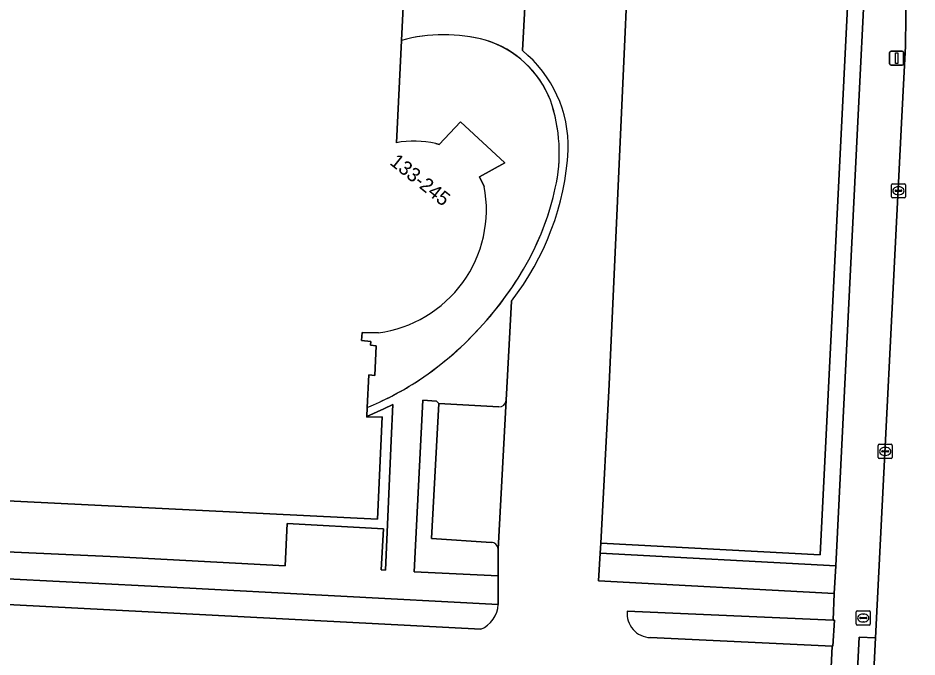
# Model space of a CAD drawing. Extents: x 161758 to 162722, y 384793 to 385405.
# Drawn here: x 162064.1 to 162127.8, y 385280.9 to 385326.1 of the extents above; entities that cross this region are included whole.
import ezdxf

# ---------------------------------------------------------------- set-up
doc = ezdxf.new("R2010")
doc.units = 0
for name, color, linetype in [('IMGEO_Brandkraan', 7, 'Continuous'), ('IMGEO_Erf', 7, 'Continuous'), ('IMGEO_Groenvoorziening', 7, 'Continuous'), ('IMGEO_Haag', 7, 'Continuous'), ('IMGEO_Kolk', 7, 'Continuous'), ('IMGEO_Lichtmast', 7, 'Continuous'), ('IMGEO_Pand', 7, 'Continuous'), ('IMGEO_Pand_nummerreeks', 7, 'Continuous'), ('IMGEO_Pand_overbouw', 7, 'Continuous'), ('IMGEO_Rijbaan_lokaal_gesloten', 7, 'Continuous'), ('IMGEO_Rijbaan_lokaal_open', 7, 'Continuous'), ('IMGEO_Voetpad_open', 7, 'Continuous')]:
    doc.layers.add(name, color=color, linetype=linetype)

msp = doc.modelspace()

# ---------------------------------------------------------------- linework, layer by layer
at = {"layer": 'IMGEO_Brandkraan'}
for p, q in [((162123.505, 385283.226), (162123.505, 385284.078)), ((162123.58, 385284.152), (162124.432, 385284.152)), ((162123.764, 385283.646), (162123.764, 385283.658)), ((162124.202, 385283.609), (162123.804, 385283.609)), ((162123.807, 385283.695), (162124.205, 385283.695)), ((162123.993, 385283.932), (162124.018, 385283.932)), ((162124.248, 385283.658), (162124.248, 385283.646)), ((162124.506, 385284.078), (162124.506, 385283.226)), ((162124.432, 385283.152), (162123.58, 385283.152)), ((162124.016, 385283.372), (162123.991, 385283.372))]:
    msp.add_line(p, q, dxfattribs=at)
for points in [[(162123.505, 385283.226), (162123.505, 385284.078)], [(162123.58, 385284.152), (162124.432, 385284.152)], [(162124.506, 385284.078), (162124.506, 385283.226)], [(162124.432, 385283.152), (162123.58, 385283.152)]]:
    msp.add_lwpolyline(points, dxfattribs=at)
for centre, radius, start, end in [((162123.582, 385284.076), 0.0765, 91.55205, 178.44795), ((162123.582, 385284.076), 0.0765, 91.55205, 178.44795), ((162123.804, 385283.655), 0.0403, 85.87752, 175.75265), ((162123.801, 385283.645), 0.0366, 178.93798, 274.71019), ((162124.205, 385283.652), 0.043, 264.86636, 352.45326), ((162124.209, 385283.657), 0.0386, 1.73085, 96.63898), ((162124.43, 385284.076), 0.0765, 1.55205, 88.44795), ((162124.43, 385284.076), 0.0765, 1.55205, 88.44795), ((162123.582, 385283.228), 0.0765, 181.55205, 268.44795), ((162123.582, 385283.228), 0.0765, 181.55205, 268.44795), ((162124.43, 385283.228), 0.0765, 271.55205, 358.44795), ((162124.43, 385283.228), 0.0765, 271.55205, 358.44795)]:
    msp.add_arc(centre, radius, start, end, dxfattribs=at)
for centre, major_axis, ratio, start_param, end_param in [((162123.992, 385283.652), (-0.387, 0.002), 0.722429, 4.712389, 7.853982), ((162124.017, 385283.652), (-0.39, 0.002), 0.717154, 1.570796, 4.712389)]:
    msp.add_ellipse(centre, major_axis=major_axis, ratio=ratio, start_param=start_param, end_param=end_param, dxfattribs=at)
at = {"layer": 'IMGEO_Erf'}
for points in [[(162123.76, 385344.448), (162124.058, 385351.671), (162110.642, 385351.717), (162108.333, 385351.725), (162106.002, 385300.194), (162105.398, 385288.95), (162120.957, 385288.114)], [(162090.663, 385298.763), (162090.024, 385298.468), (162088.823, 385297.914), (162088.821, 385297.876), (162089.919, 385297.91), (162089.575, 385290.639), (162056.667, 385292.277), (162056.492, 385288.65), (162071.152, 385287.989), (162083.046, 385287.356), (162083.181, 385290.342), (162090.009, 385289.962), (162089.851, 385287.051), (162090.151, 385287.029), (162090.553, 385296.234)]]:
    msp.add_lwpolyline(points, close=True, dxfattribs=at)
for points in [[(162091.282, 385324.562), (162090.923, 385317.316)], [(162093.708, 385317.259), (162093.944, 385317.186), (162095.457, 385318.788), (162098.608, 385315.88), (162096.803, 385314.905), (162097.15, 385314.213)], [(162089.645, 385303.85), (162088.504, 385303.874), (162088.454, 385303.297), (162089.102, 385303.241), (162089.079, 385302.969), (162089.498, 385302.937), (162089.397, 385300.836), (162088.976, 385300.882), (162088.856, 385298.567)], [(162098.124, 385288.523), (162098.709, 385299.073)], [(162098.178, 385298.601), (162093.924, 385298.849), (162093.402, 385289.271), (162097.627, 385289.009)]]:
    msp.add_lwpolyline(points, dxfattribs=at)
for centre, radius, start, end in [((162094.285, 385313.577), 11.388, 74.92268, 105.28864), ((162095.191, 385317.758), 7.118, 21.08722, 73.21442), ((162091.239, 385316.597), 11.229, 347.07124, 19.35561), ((162092.174, 385310.356), 7.071, 77.46799, 100.18702), ((162088.482, 385312.592), 8.819, 277.58057, 10.59448), ((162082.963, 385318.319), 19.681, 331.80184, 347.57767), ((162078.804, 385320.829), 24.534, 317.24393, 331.22338), ((162079.371, 385320.218), 23.702, 302.88638, 317.39865), ((162080.906, 385318.123), 21.11, 292.12183, 302.47473), ((162098.207, 385299.103), 0.503, 266.67466, 356.59242), ((162097.639, 385288.524), 0.485, 359.86402, 91.41823)]:
    msp.add_arc(centre, radius, start, end, dxfattribs=at)
at = {"layer": 'IMGEO_Groenvoorziening'}
for points in [[(162124.937, 385344.85), (162125.282, 385351.667), (162124.058, 385351.671), (162123.76, 385344.448), (162120.957, 385288.114), (162105.398, 385288.95), (162105.36, 385288.235), (162122.052, 385287.335), (162123.635, 385319.287), (162124.144, 385329.185)], [(162122.052, 385287.335), (162105.36, 385288.235), (162105.255, 385286.288), (162121.956, 385285.388)]]:
    msp.add_lwpolyline(points, close=True, dxfattribs=at)
for points in [[(162093.924, 385298.849), (162093.769, 385299.017), (162092.793, 385299.072), (162092.186, 385286.922), (162098.133, 385286.639), (162098.124, 385288.523)], [(162097.627, 385289.009), (162093.402, 385289.271), (162093.924, 385298.849)], [(162098.143, 385284.617), (162074.929, 385285.836), (162055.428, 385286.819), (162055.318, 385285.029), (162056.316, 385284.979), (162056.544, 385284.967), (162096.901, 385282.85)], [(162108.914, 385282.264), (162121.795, 385281.655), (162121.859, 385281.652), (162121.967, 385283.492), (162121.873, 385283.503), (162107.279, 385284.136)]]:
    msp.add_lwpolyline(points, dxfattribs=at)
for centre, radius, start, end in [((162097.639, 385288.524), 0.485, 359.86402, 91.41823), ((162096.073, 385284.752), 2.075, 293.52768, 356.26661), ((162108.974, 385283.967), 1.704, 174.29511, 267.97265)]:
    msp.add_arc(centre, radius, start, end, dxfattribs=at)
at = {"layer": 'IMGEO_Haag'}
msp.add_lwpolyline([(162124.937, 385344.85), (162125.282, 385351.667), (162124.058, 385351.671), (162123.76, 385344.448), (162120.957, 385288.114), (162105.398, 385288.95), (162105.36, 385288.235), (162122.052, 385287.335), (162123.635, 385319.287), (162124.144, 385329.185)], close=True, dxfattribs=at)
at = {"layer": 'IMGEO_Kolk'}
for p, q in [((162125.999, 385313.483), (162125.999, 385314.335)), ((162126.074, 385314.409), (162126.926, 385314.409)), ((162126.487, 385314.189), (162126.512, 385314.189)), ((162127, 385314.335), (162127, 385313.483)), ((162126.258, 385313.903), (162126.258, 385313.915)), ((162126.696, 385313.866), (162126.298, 385313.866)), ((162126.301, 385313.952), (162126.699, 385313.952)), ((162126.51, 385313.629), (162126.485, 385313.629)), ((162126.742, 385313.915), (162126.742, 385313.903)), ((162126.926, 385313.409), (162126.074, 385313.409)), ((162125.063, 385295.025), (162125.063, 385295.877)), ((162125.138, 385295.951), (162125.99, 385295.951)), ((162125.551, 385295.731), (162125.576, 385295.731)), ((162126.064, 385295.877), (162126.064, 385295.025)), ((162125.322, 385295.445), (162125.322, 385295.457)), ((162125.76, 385295.408), (162125.362, 385295.408)), ((162125.365, 385295.494), (162125.763, 385295.494)), ((162125.574, 385295.171), (162125.549, 385295.171)), ((162125.806, 385295.457), (162125.806, 385295.445)), ((162125.99, 385294.951), (162125.138, 385294.951))]:
    msp.add_line(p, q, dxfattribs=at)
for points in [[(162125.999, 385313.483), (162125.999, 385314.335)], [(162126.074, 385314.409), (162126.926, 385314.409)], [(162127, 385314.335), (162127, 385313.483)], [(162126.926, 385313.409), (162126.074, 385313.409)], [(162125.063, 385295.025), (162125.063, 385295.877)], [(162125.138, 385295.951), (162125.99, 385295.951)], [(162126.064, 385295.877), (162126.064, 385295.025)], [(162125.99, 385294.951), (162125.138, 385294.951)]]:
    msp.add_lwpolyline(points, dxfattribs=at)
for centre, radius, start, end in [((162126.076, 385314.333), 0.0765, 91.55205, 178.44795), ((162126.076, 385314.333), 0.0765, 91.55205, 178.44795), ((162126.924, 385314.333), 0.0765, 1.55205, 88.44795), ((162126.924, 385314.333), 0.0765, 1.55205, 88.44795), ((162126.298, 385313.912), 0.0403, 85.87752, 175.75265), ((162126.295, 385313.902), 0.0366, 178.93798, 274.71019), ((162126.699, 385313.909), 0.043, 264.86636, 352.45326), ((162126.703, 385313.914), 0.0386, 1.73085, 96.63898), ((162126.076, 385313.485), 0.0765, 181.55205, 268.44795), ((162126.076, 385313.485), 0.0765, 181.55205, 268.44795), ((162126.924, 385313.485), 0.0765, 271.55205, 358.44795), ((162126.924, 385313.485), 0.0765, 271.55205, 358.44795), ((162125.14, 385295.875), 0.0765, 91.55205, 178.44795), ((162125.14, 385295.875), 0.0765, 91.55205, 178.44795), ((162125.988, 385295.875), 0.0765, 1.55205, 88.44795), ((162125.988, 385295.875), 0.0765, 1.55205, 88.44795), ((162125.362, 385295.454), 0.0403, 85.87752, 175.75265), ((162125.359, 385295.444), 0.0366, 178.93798, 274.71019), ((162125.763, 385295.451), 0.043, 264.86636, 352.45326), ((162125.767, 385295.456), 0.0386, 1.73085, 96.63898), ((162125.14, 385295.027), 0.0765, 181.55205, 268.44795), ((162125.14, 385295.027), 0.0765, 181.55205, 268.44795), ((162125.988, 385295.027), 0.0765, 271.55205, 358.44795), ((162125.988, 385295.027), 0.0765, 271.55205, 358.44795)]:
    msp.add_arc(centre, radius, start, end, dxfattribs=at)
for centre, major_axis, ratio, start_param, end_param in [((162126.486, 385313.909), (-0.387, 0.002), 0.722429, 4.712389, 7.853982), ((162126.511, 385313.909), (-0.39, 0.002), 0.717154, 1.570796, 4.712389), ((162125.55, 385295.451), (-0.387, 0.002), 0.722429, 4.712389, 7.853982), ((162125.575, 385295.451), (-0.39, 0.002), 0.717154, 1.570796, 4.712389)]:
    msp.add_ellipse(centre, major_axis=major_axis, ratio=ratio, start_param=start_param, end_param=end_param, dxfattribs=at)
at = {"layer": 'IMGEO_Lichtmast'}
for p, q in [((162125.976, 385323.801), (162126.766, 385323.801)), ((162126.766, 385323.801), (162125.976, 385323.801)), ((162125.876, 385322.901), (162125.876, 385323.701)), ((162125.876, 385323.701), (162125.876, 385322.901)), ((162126.866, 385323.701), (162126.866, 385322.901)), ((162126.866, 385322.901), (162126.866, 385323.701)), ((162126.766, 385322.801), (162125.976, 385322.801)), ((162125.976, 385322.801), (162126.766, 385322.801))]:
    msp.add_line(p, q, dxfattribs=at)
msp.add_lwpolyline([(162126.296, 385323.676), (162126.446, 385323.676), (162126.446, 385322.926), (162126.296, 385322.926), (162126.296, 385323.676)], dxfattribs=at)
for centre, start, end in [((162125.976, 385323.701), 90, 180), ((162125.976, 385323.701), 90, 180), ((162126.766, 385323.701), 0, 90), ((162126.766, 385323.701), 360, 90), ((162125.976, 385322.901), 180, 270), ((162125.976, 385322.901), 180, 270), ((162126.766, 385322.901), 270, 0), ((162126.766, 385322.901), 270, 0)]:
    msp.add_arc(centre, 0.1, start, end, dxfattribs=at)
at = {"layer": 'IMGEO_Pand'}
for points in [[(162091.282, 385324.562), (162092.129, 385341.645), (162076.599, 385342.392), (162069.876, 385342.73), (162066.145, 385342.918), (162059.203, 385343.267), (162057.875, 385316.893), (162057.335, 385306.161), (162056.667, 385292.277), (162089.575, 385290.639), (162089.919, 385297.91), (162088.821, 385297.876), (162088.823, 385297.914), (162088.856, 385298.567), (162088.976, 385300.882), (162089.397, 385300.836), (162089.498, 385302.937), (162089.079, 385302.969), (162089.102, 385303.241), (162088.454, 385303.297), (162088.504, 385303.874), (162089.645, 385303.85)], [(162090.923, 385317.316), (162091.282, 385324.562)], [(162097.15, 385314.213), (162096.803, 385314.905), (162098.608, 385315.88), (162095.457, 385318.788), (162093.944, 385317.186), (162093.708, 385317.259)]]:
    msp.add_lwpolyline(points, dxfattribs=at)
for centre, radius, start, end in [((162092.174, 385310.356), 7.071, 77.46799, 100.18702), ((162088.482, 385312.592), 8.819, 277.58057, 10.59448)]:
    msp.add_arc(centre, radius, start, end, dxfattribs=at)
at = {"layer": 'IMGEO_Pand_overbouw'}
for points in [[(162089.645, 385303.85), (162088.504, 385303.874), (162088.454, 385303.297), (162089.102, 385303.241), (162089.079, 385302.969), (162089.498, 385302.937), (162089.397, 385300.836), (162088.976, 385300.882), (162088.856, 385298.567), (162089.296, 385298.751), (162089.731, 385298.945), (162090.162, 385299.15), (162090.588, 385299.364), (162091.01, 385299.587), (162091.426, 385299.82), (162091.836, 385300.063), (162092.241, 385300.314), (162092.863, 385300.731), (162093.473, 385301.168), (162094.07, 385301.624), (162094.652, 385302.099), (162095.218, 385302.593), (162095.769, 385303.103), (162096.302, 385303.631), (162096.818, 385304.174), (162097.317, 385304.73), (162097.799, 385305.302), (162098.264, 385305.888), (162098.711, 385306.489), (162099.14, 385307.104), (162099.549, 385307.731), (162099.938, 385308.369), (162100.308, 385309.019), (162100.617, 385309.62), (162100.906, 385310.232), (162101.173, 385310.855), (162101.42, 385311.487), (162101.644, 385312.127), (162101.846, 385312.774), (162102.026, 385313.427), (162102.183, 385314.085), (162102.264, 385314.468), (162102.331, 385314.855), (162102.386, 385315.245), (162102.427, 385315.639), (162102.453, 385316.034), (162102.466, 385316.431), (162102.465, 385316.829), (162102.45, 385317.227), (162102.421, 385317.624), (162102.377, 385318.019), (162102.32, 385318.412), (162102.249, 385318.803), (162102.165, 385319.189), (162102.067, 385319.571), (162101.956, 385319.948), (162101.833, 385320.319), (162101.682, 385320.682), (162101.508, 385321.04), (162101.313, 385321.391), (162101.096, 385321.733), (162100.859, 385322.065), (162100.602, 385322.384), (162100.326, 385322.688), (162100.032, 385322.977), (162099.722, 385323.248), (162099.398, 385323.5), (162099.06, 385323.733), (162098.712, 385323.944), (162098.355, 385324.135), (162097.99, 385324.303), (162097.62, 385324.449), (162097.247, 385324.573), (162096.884, 385324.664), (162096.518, 385324.744), (162096.148, 385324.812), (162095.775, 385324.867), (162095.399, 385324.911), (162095.022, 385324.941), (162094.643, 385324.96), (162094.264, 385324.965), (162093.884, 385324.958), (162093.506, 385324.938), (162093.128, 385324.906), (162092.753, 385324.862), (162092.38, 385324.805), (162092.01, 385324.735), (162091.644, 385324.654), (162091.282, 385324.562)], [(162091.282, 385324.562), (162090.923, 385317.316)], [(162093.708, 385317.259), (162093.944, 385317.186), (162095.457, 385318.788), (162098.608, 385315.88), (162096.803, 385314.905), (162097.15, 385314.213)]]:
    msp.add_lwpolyline(points, dxfattribs=at)
for centre, radius, start, end in [((162092.174, 385310.356), 7.071, 77.46799, 100.18702), ((162088.482, 385312.592), 8.819, 277.58057, 10.59448)]:
    msp.add_arc(centre, radius, start, end, dxfattribs=at)
at = {"layer": 'IMGEO_Rijbaan_lokaal_gesloten'}
msp.add_lwpolyline([(162127.185, 385353.161), (162127.085, 385332.496), (162126.992, 385324.158), (162126.732, 385319.163), (162124.878, 385282.238), (162124.469, 385274.256), (162122.219, 385228.776), (162121.802, 385220.491), (162113.455, 385051.843), (162119.917, 385051.572), (162121.833, 385090.293), (162122.159, 385097.081), (162128.368, 385221.63)], dxfattribs=at)
at = {"layer": 'IMGEO_Rijbaan_lokaal_open'}
for points in [[(162107.279, 385284.136), (162121.873, 385283.503), (162121.956, 385285.388), (162105.255, 385286.288), (162105.36, 385288.235), (162105.398, 385288.95), (162106.002, 385300.194), (162108.333, 385351.725), (162060.278, 385351.889), (162052.58, 385351.915), (162020.661, 385350.428), (162018.925, 385350.398), (162017.539, 385350.338), (162014.525, 385350.243), (162013.696, 385350.227), (161993.578, 385349.878)], [(162100.82, 385343.135), (162100.702, 385341.023), (162100.041, 385327.331), (162099.856, 385323.836)], [(162099.078, 385306.092), (162098.709, 385299.073), (162098.124, 385288.523), (162098.133, 385286.639), (162098.143, 385284.617)], [(162096.901, 385282.85), (162056.544, 385284.967), (162056.316, 385284.979), (162055.318, 385285.029), (162053.915, 385285.1), (162053.849, 385285.103), (162052.057, 385285.194)], [(162050.835, 385279.171), (162053.548, 385279.049), (162055.602, 385278.957), (162056.237, 385278.926), (162083.133, 385277.615), (162121.521, 385275.665), (162121.795, 385281.655), (162108.914, 385282.264)]]:
    msp.add_lwpolyline(points, dxfattribs=at)
for centre, radius, start, end in [((162094.307, 385317.007), 8.799, 358.52687, 50.90077), ((162083.804, 385317.946), 19.335, 322.18614, 356.54559), ((162096.073, 385284.752), 2.075, 293.52768, 356.26661), ((162108.974, 385283.967), 1.704, 174.29511, 267.97265)]:
    msp.add_arc(centre, radius, start, end, dxfattribs=at)
at = {"layer": 'IMGEO_Voetpad_open'}
for points in [[(162125.941, 385359.83), (162125.801, 385360.29), (162125.588, 385360.595), (162125.235, 385360.645), (162124.231, 385360.587), (162123.952, 385354.907), (162123.946, 385353.106), (162125.355, 385353.101), (162125.282, 385351.667), (162124.937, 385344.85), (162124.144, 385329.185), (162123.635, 385319.287), (162122.052, 385287.335), (162121.956, 385285.388), (162121.873, 385283.503), (162121.967, 385283.492), (162121.859, 385281.652), (162121.795, 385281.655), (162121.521, 385275.665), (162120.58, 385255.067), (162119.21, 385227.479)], [(162121.802, 385220.491), (162121.292, 385220.517), (162121.7, 385228.795), (162122.219, 385228.776), (162124.469, 385274.256), (162123.313, 385274.317), (162123.721, 385282.3), (162124.878, 385282.238), (162126.732, 385319.163), (162126.992, 385324.158), (162127.085, 385332.496), (162127.185, 385353.161)], [(162069.958, 385344.683), (162069.876, 385342.73), (162076.599, 385342.392), (162092.129, 385341.645), (162091.282, 385324.562)], [(162099.856, 385323.836), (162100.041, 385327.331), (162095.229, 385327.577), (162095.865, 385340.834)], [(162098.709, 385299.073), (162099.078, 385306.092)], [(162088.856, 385298.567), (162088.823, 385297.914), (162090.024, 385298.468), (162090.663, 385298.763), (162090.553, 385296.234), (162090.151, 385287.029), (162089.851, 385287.051), (162090.009, 385289.962), (162083.181, 385290.342), (162083.046, 385287.356), (162071.152, 385287.989), (162056.492, 385288.65), (162054.142, 385288.756), (162054.026, 385286.89), (162055.428, 385286.819), (162074.929, 385285.836), (162098.143, 385284.617), (162098.133, 385286.639), (162092.186, 385286.922), (162092.793, 385299.072), (162093.769, 385299.017), (162093.924, 385298.849), (162098.178, 385298.601)]]:
    msp.add_lwpolyline(points, dxfattribs=at)
msp.add_lwpolyline([(162124.878, 385282.238), (162123.721, 385282.3), (162123.313, 385274.317), (162124.469, 385274.256)], close=True, dxfattribs=at)
for centre, radius, start, end in [((162094.285, 385313.577), 11.388, 74.92268, 105.28864), ((162095.191, 385317.758), 7.118, 21.08722, 73.21442), ((162094.307, 385317.007), 8.799, 358.52687, 50.90077), ((162091.239, 385316.597), 11.229, 347.07124, 19.35561), ((162083.804, 385317.946), 19.335, 322.18614, 356.54559), ((162082.963, 385318.319), 19.681, 331.80184, 347.57767), ((162078.804, 385320.829), 24.534, 317.24393, 331.22338), ((162079.371, 385320.218), 23.702, 302.88638, 317.39865), ((162080.906, 385318.123), 21.11, 292.12183, 302.47473), ((162098.207, 385299.103), 0.503, 266.67466, 356.59242)]:
    msp.add_arc(centre, radius, start, end, dxfattribs=at)

# ---------------------------------------------------------------- texts
at = {"layer": 'IMGEO_Pand_nummerreeks'}
msp.add_text('133-245', height=1, rotation=321.41702, dxfattribs=at).set_placement((162090.391, 385315.825))

doc.saveas('drawing.dxf')
